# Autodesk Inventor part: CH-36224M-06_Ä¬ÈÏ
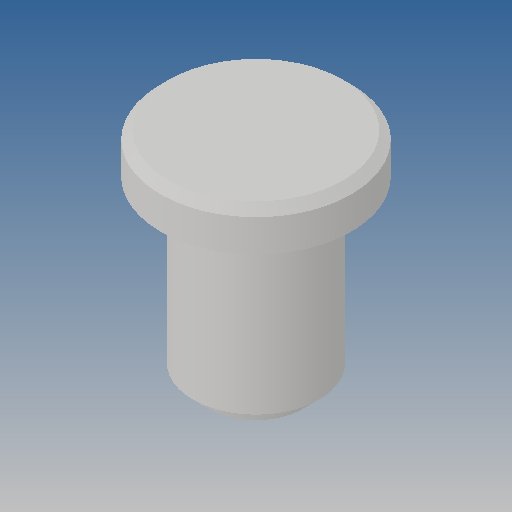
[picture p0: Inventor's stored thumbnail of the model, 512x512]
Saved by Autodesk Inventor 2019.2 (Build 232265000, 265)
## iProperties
Created: 2010-06
Part Number: CH-36224M-06_Ä¬ÈÏ
Material: Ogólny
Document SubType Name: Modeling
Designer: CADENGINEERING4
Density: 1 g/cm^3
Appearance: Domyślna
Author: CADENGINEERING4
Revision Number: ÈÎºÎ
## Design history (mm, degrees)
feature "NONE"
node "Bryła1"
